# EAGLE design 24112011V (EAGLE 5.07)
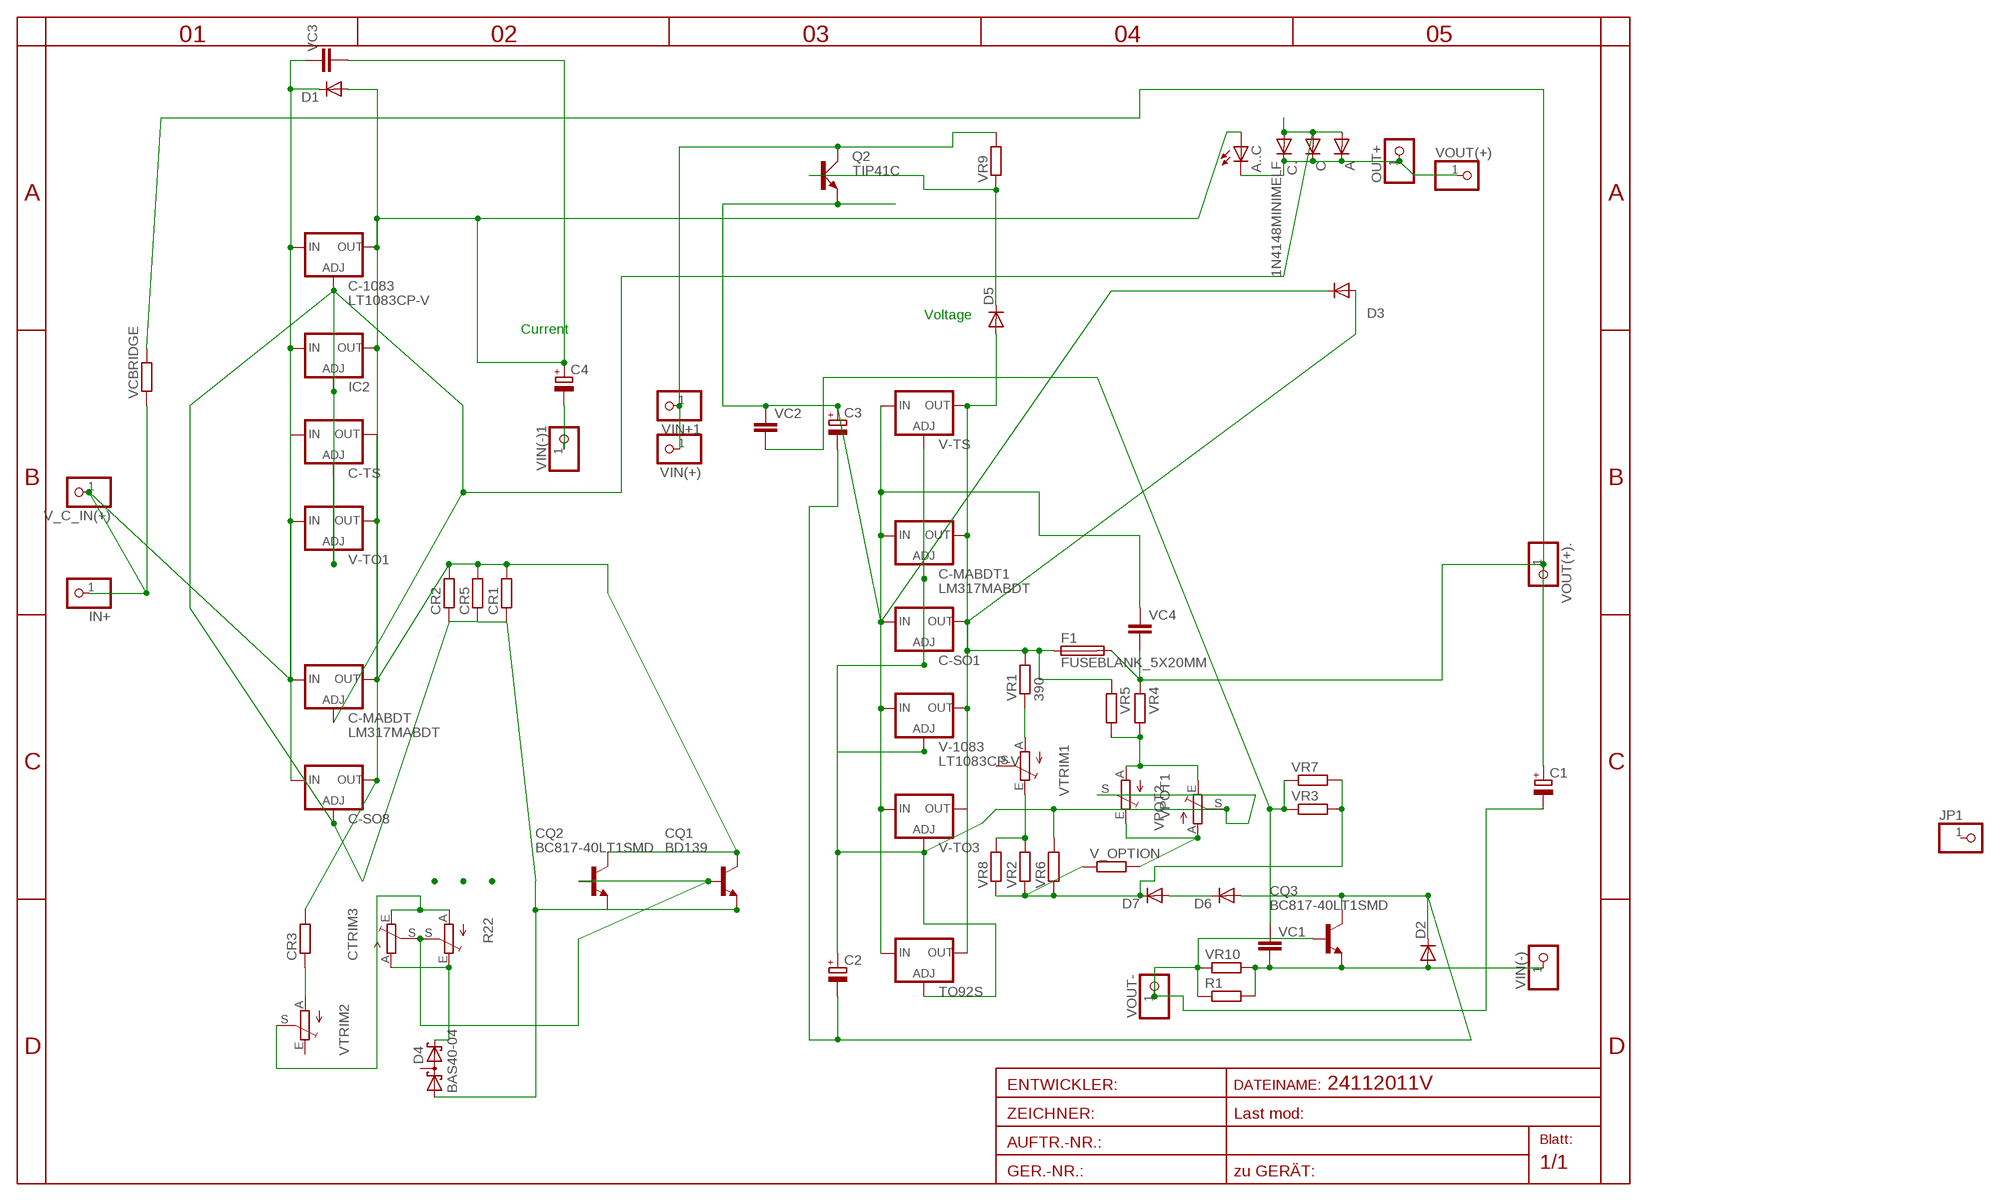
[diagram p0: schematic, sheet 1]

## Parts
A  DIODE-TO220V  [TO220ACS]
A..C  LED3MM  [LED3MM]
C  DIODE-SMB  [SMB]
C1  CPOL-EUE5-8.5  [E5-8,5]
C2  CPOL-EUE2.5-6  [E2,5-6]
C3  CPOL-EUE2.5-6  [E2,5-6]
C4  CPOL-EUE5-6  [E5-6]
C-1083  LT1083CP-V  [TO247S]
C-MABDT  LM317MABDT  [DPACK]
C-MABDT1  LM317MABDT  [DPACK]
C-SO1  LM317LM-OUTPIN7  [SO08]
C-SO8  LM317LM-OUTPIN7  [SO08]
C-TS  LM317TS  [317TS]
C.  1N4148MINIMELF  [MINIMELF]
CQ1  BD139  [TO126V]
CQ2  BC817-40LT1SMD  [SOT23-BEC]
CQ3  BC817-40LT1SMD  [SOT23-BEC]
CR1  R-EU_R5025  [R5025]
CR2  R-EU_R1206  [R1206]
CR3  R-EU_0204/5  [0204/5]
CR5  R-EU_R1210  [R1210]
CTRIM3  TRIM_EU-EVND_H  [EVND8AA]
D1  DIODE-MINIMELF  [MINIMELF]
D2  DIODE-MINIMELF  [MINIMELF]
D3  DIODE-MINIMELF  [MINIMELF]
D4  BAS40-04  [SOT23]
D5  DIODE-MINIMELF  [MINIMELF]
D6  DIODE-MINIMELF  [MINIMELF]
D7  DIODE-MINIMELF  [MINIMELF]
F1  FUSEBLANK_5X20MM  [FUSE_HOLDER_5X20MM]
IC2  LM317LZS  [TO92S]
IN+  PINHD-1X1  [1X01]
JP1  PINHD-1X10MM8  [1X01]
OUT+  PINHD-1X1  [1X01]
Q2  TIP41C  [TO220AV]
R1  R-EU_  [CERAM40]
R22  TRIM_EU-RAND160  [RANDL]
TO92S  LM317LZS  [TO92S]
V-1083  LT1083CP-V  [TO247S]
V-TO1  LM317-TO3  [TO3-K02]
V-TO3  LM317-TO3  [TO3-K02]
V-TS  LM317TS  [317TS]
V_C_IN(+)  PINHD-1X10MM8  [1X01]
V_OPTION  R-EU_0204/2V  [0204V]
VC1  C-EU050-025X075  [C050-025X075]
VC2  C-EU050-025X075  [C050-025X075]
VC3  C-EU050-025X075  [C050-025X075]
VC4  C-EUC1206  [C1206]
VCBRIDGE  R-EU_R0402  [R0402]
VIN(+)  PINHD-1X10MM8  [1X01]
VIN(-)  PINHD-1X1  [1X01]
VIN(-)1  PINHD-1X1  [1X01]
VIN+1  PINHD-1X1  [1X01]
VOUT(+)  PINHD-1X10MM8  [1X01]
VOUT(+).  PINHD-1X10MM8  [1X01]
VOUT-  PINHD-1X10MM8  [1X01]
VPOT1  TRIM_EU-RAND160  [RANDL]
VPOT2  TRIM_EU-S64W  [S64W]
VR1  390  R-EU_0207/15  [0207/15]
VR2  R-EU_0204/2V  [0204V]
VR3  R-EU_0204/5  [0204/5]
VR4  R-EU_R1206  [R1206]
VR5  R-EU_R1206  [R1206]
VR6  R-EU_R1206  [R1206]
VR7  R-EU_R1206  [R1206]
VR8  R-EU_R1206  [R1206]
VR9  R-EU_R1206  [R1206]
VR10  R-EU_0617/17  [0617/17]
VTRIM1  TRIM_EU-EVND_H  [EVND8AA]
VTRIM2  TRIM_EU-EVND_H  [EVND8AA]

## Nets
ADJ2: C2.+ C-MABDT1.1(ADJ) C-SO1.4(ADJ) TO92S.1(ADJ) V-1083.1(ADJ) V-TO3.2(ADJ) V-TS.1(ADJ) VPOT1.S VPOT2.S VR6.2
ADJUST: A.A C-1083.1(ADJ) C-MABDT.1(ADJ) C-SO8.4(ADJ) C-TS.1(ADJ) C..A C.A CQ1.3(E) CQ2.E CR1.1 CR2.1 CR5.1 D4.1(A1) IC2.1(ADJ) V-TO1.2(ADJ)
B1: CQ1.1(B) CQ2.B CTRIM3.S R22.S
IN+1: C3.+ C-MABDT1.3(IN) C-SO1.1(IN) D3.C Q2.E TO92S.3(IN) V-1083.3(IN) V-TO3.1(IN) V-TS.3(IN) VC2.1 VC4.1
IN-: CQ3.E D2.A R1.2 VC1.2 VIN(-).1 VR10.2
INPUT+: C-1083.3(IN) C-MABDT.3(IN) C-SO8.1(IN) C-TS.3(IN) D1.C IC2.3(IN) IN+.1 V-TO1.1(IN) V_C_IN(+).1 VC3.1 VCBRIDGE.1
MINUS: CTRIM3.A D4.2(C2) R22.E
N$1: V_OPTION.2 VPOT1.E VPOT2.A
N$2: VPOT1.A VPOT2.E VR4.2 VR5.2
N$3: VR2.2 VR8.2 VTRIM1.E
N$4: VR1.1 VTRIM1.A
N$5: CTRIM3.E R22.A VTRIM2.S
N$6: CR3.1 VTRIM2.A
N$7: VC1.1 VC2.2 VR3.1 VR7.1
N$8: Q2.C VIN(+).1 VIN+1.1 VR9.2
N$9: C4.- VIN(-)1.1
N$10: D5.C Q2.B VR9.1
N$11: C1.- CQ3.B R1.1 VOUT-.1 VR10.1
N$12: D7.C V_OPTION.1 VR2.1 VR3.2 VR6.1 VR7.2 VR8.1
N$13: D6.C D7.A
OUT1: A..C.A C4.+ C-1083.2(OUT) C-MABDT.4(OUT) C-SO8.7(OUT) C-TS.2(OUT) CQ1.2(C) CQ2.C CR1.2 CR2.2 CR3.2 CR5.2 D1.A IC2.2(OUT) V-TO1.3(OUT) VC3.2
OUT2: C-MABDT1.4(OUT) C-SO1.7(OUT) D3.A D5.A F1.1 TO92S.2(OUT) V-1083.2(OUT) V-TO3.3(OUT) V-TS.2(OUT) VR1.2 VR5.1
OUT+: A..C.K(C) A.C C..C C.C OUT+.1 VOUT(+).1
VIRT-: C2.- C3.- CQ3.C D2.C D6.A
VOUT+: C1.+ F1.2 VC4.2 VCBRIDGE.2 VOUT(+)..1 VR4.1
Unconnected: D4.3(C1A2) JP1.1 VTRIM1.S VTRIM2.E

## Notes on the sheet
- Voltage
- Current

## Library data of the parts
A C D1-D3 D5-D7 = diode:DIODE-: DIODE
A..C = led:LED: LED
C1-C4 = rcl:CPOL-EU: POLARIZED CAPACITOR, European symbol
C-1083 V-1083 = linear-technology-2:LT1083*: 7.5A Low Dropout Positive Adjustable Regulators
C-MABDT C-MABDT1 = v-reg:LM317?*: 500 mA Adjustable Output Positive Voltage Regulator Source: http://www.onsemi.co.jp .. LM317M-D.PDF
C-SO1 C-SO8 IC2 TO92S = v-reg-3:LM317L: Adjustable Voltage Regulator, 1.2V to 37V, 100mA
C-TS V-TS = v-reg:LM317TS: VOLTAGE REGULATOR
C. = diode-1:1N4148: DIODE
CQ1 = transistor-npn:BD139*: NPN Transistor
CQ2 CQ3 = transistor-npn:BC817*: NPN Transistor
CR1-CR3 CR5 V_OPTION VCBRIDGE VR1-VR10 = rcl-2:R-EU_: RESISTOR, European symbol
CTRIM3 R22 VPOT1 VPOT2 VTRIM1 VTRIM2 = pot:TRIM_EU-: POTENTIOMETER
D4 = diode:BAS40-04: Silicon Schottky Diodes General-purpose diode for high-speed switching
F1 = fuse:FUSE: Fuse
IN+ OUT+ VIN(-) VIN(-)1 VIN+1 = pinhead(2):PINHD-1X1: PIN HEADER
JP1 V_C_IN(+) VIN(+) VOUT(+) VOUT(+). VOUT- = pinhead:PINHD-1X1: PIN HEADER
Q2 = transistor-power:TIP41C: NPN TRANSISTOR
R1 = rcl:R-EU_: RESISTOR, European symbol
V-TO1 V-TO3 = v-reg:LM317-TO3: VOLTAGE REGULATOR
VC1-VC4 = rcl:C-EU: CAPACITOR, European symbol

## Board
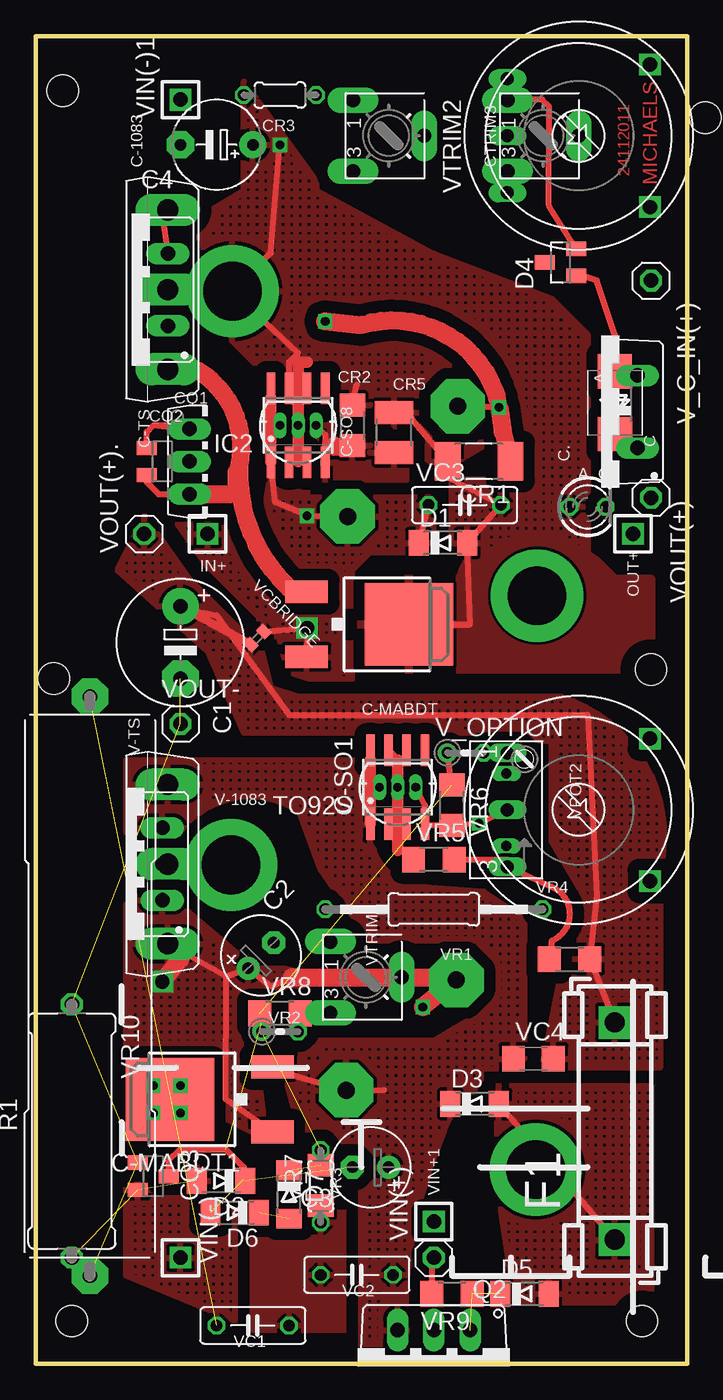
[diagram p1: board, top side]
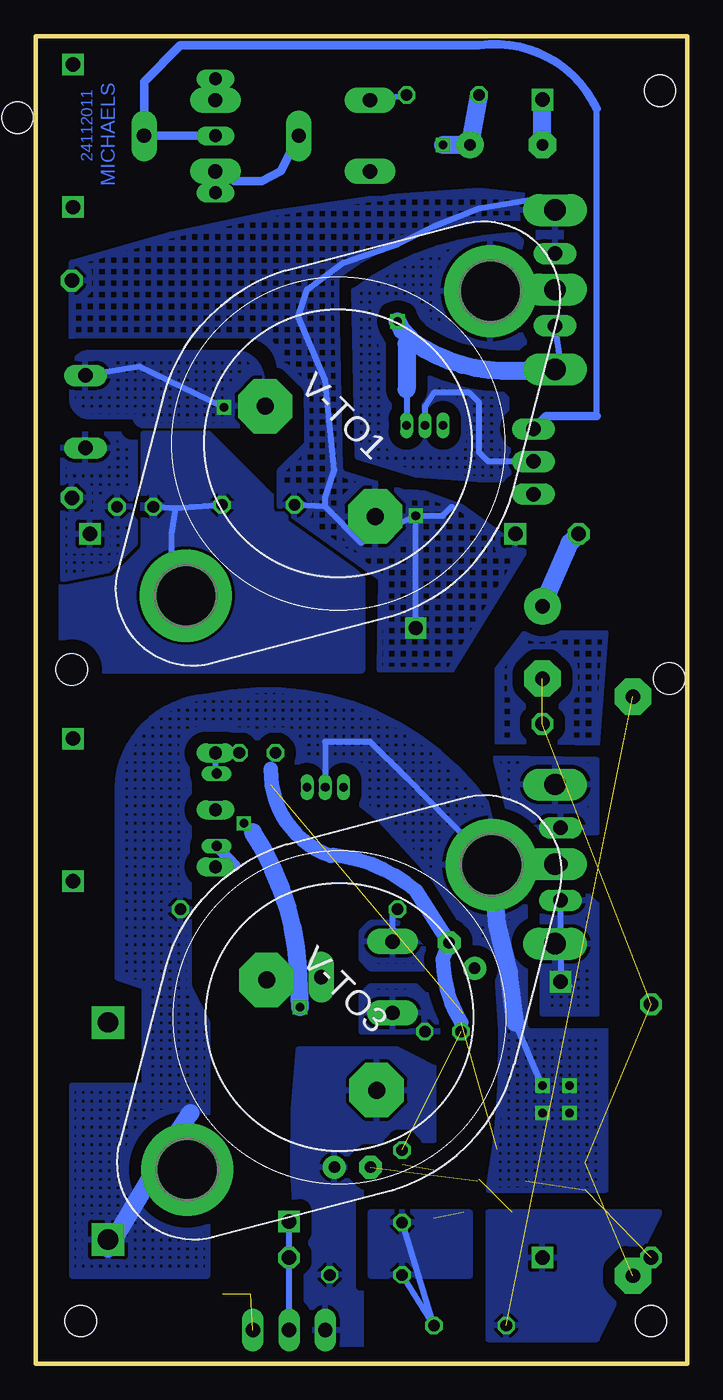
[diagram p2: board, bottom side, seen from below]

Size 45.72 x 93.18 mm. Coordinates in mm from the lower left corner, seen from the top.
Outline: 45.72,0 45.72,93.18 0,93.18 0,0 45.72,0
Copper layers (1*16): Top 0.035mm / dielectric 1.5mm / Bottom 0.035mm
Design rules "default *": minimum track width 10mil, minimum drill 24mil, track to track 8mil, track to pad 8mil, pad to pad 8mil, via to via 8mil, smd to smd 8mil, copper to edge 40mil, drill to drill 8mil, minimum pad ring 1mil, minimum via ring 8mil, stop-mask expansion 4mil, vias tented up to drill 0mil, thermal gap 10mil
Holes 2.2 mm at 46.99,87.46 1.27,48.09 43.18,48.73 1.91,89.37 42.55,3.01 2.54,3.01

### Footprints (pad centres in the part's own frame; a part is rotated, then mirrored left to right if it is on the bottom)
TO220ACS = drill 1.016 long: A 2.54,-2.54; C -2.54,-2.54
LED3MM = drill 0.813 octagon: A -1.27,0; K 1.27,0
SMB = smd 2.4 x 2.4: A 2.2,0; C -2.2,0
E5-8,5 = drill 1.016 pad 2.54 round: + -2.54,0 | drill 1.016 pad 2.54 octagon: - 2.54,0
E2,5-6 = drill 0.813 pad 1.6 round: + -1.27,0 | drill 0.813 pad 1.6 octagon: - 1.27,0
E5-6 = drill 0.813 pad 1.905 round: + -2.54,0 | drill 0.813 pad 1.905 octagon: - 2.54,0
TO247S = drill 1.499 long: 1 -5.588,-2.921; 2 0,-2.921; 3 5.588,-2.921
DPACK = smd 1.6 x 3: 1 -2.28,-4.8; 3 2.28,-4.8 | smd 5.8 x 6.2: 4 0,2.38
SO08 = smd 0.6 x 2.2: 1 -1.905,-2.6; 2 -0.635,-2.6; 3 0.635,-2.6; 4 1.905,-2.6; 5 1.905,2.6; 6 0.635,2.6; 7 -0.635,2.6; 8 -1.905,2.6
317TS = drill 1.016 long: 1 -2.54,-2.54; 2 0,-2.54; 3 2.54,-2.54
MINIMELF = smd 1.4 x 1.8: A 1.7,0; C -1.7,0
TO126V = drill 1.016 long: 1 -2.286,-1.27; 2 0,-1.27; 3 2.286,-1.27
SOT23-BEC = smd 1 x 1.4: B -0.95,-1.1; C 0,1.1; E 0.95,-1.1
R5025 = smd 1.8 x 2.7: 1 -2.2,0; 2 2.2,0
R1206 = smd 1.6 x 1.803: 1 -1.422,0; 2 1.422,0
0204/5 = drill 0.813 octagon: 1 -2.54,0; 2 2.54,0
R1210 = smd 1.6 x 2.7: 1 -1.4,0; 2 1.4,0
EVND8AA = drill 1 pad 1.778 long: A -2.5,-2.5; E 2.5,-2.5; S 0,2.5
SOT23 = smd 1 x 1.4: 1 -0.95,-1.1; 2 0.95,-1.1; 3 0,1.1
FUSE_HOLDER_5X20MM = drill 1.422 pad 2.286 square: 1 0,0; 2 15.24,0
TO92S = drill 0.6 pad 0.813 long: 1 -1.27,0; 2 0,0; 3 1.27,0
1X01 = drill 1.016 square: 1 0,0
1X01' = drill 1.016 octagon: 1 0,0
TO220AV = drill 1.016 long: B -2.54,-2.54; C 0,-2.54; E 2.54,-2.54
CERAM40 = drill 1 pad 2.54 octagon: 1 -20.32,0; 2 20.32,0
RANDL = drill 0.9 long: A -4,5; E 4,5; S 0,5 | drill 1 square: P$1 -5,-5; P$2 5,-5
TO3-K02 = drill 1.194 pad 3.81 octagon: 1 -1.778,-5.461; 2 -1.778,5.461 | drill 4.115 pad 6.477 round: 3 15.113,0; 3@ -15.113,0
0204V = drill 0.813 octagon: 1 -1.27,0; 2 1.27,0
C050-025X075 = drill 0.813 octagon: 1 -2.54,0; 2 2.54,0
C1206 = smd 1.6 x 1.8: 1 -1.4,0; 2 1.4,0
R0402 = smd 0.7 x 0.9: 1 -0.65,0; 2 0.65,0
S64W = drill 0.7 long: A 2.54,1.27; E -2.54,1.27; S 0,1.27
0207/15 = drill 0.813 octagon: 1 -7.62,0; 2 7.62,0
0617/17 = drill 1.016 octagon: 1 -8.89,0; 2 8.89,0

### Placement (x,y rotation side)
A  39.69,66.83 90 top
A..C  38.73,60.16 0 top
C  40.64,67.46 90 top
C1  10.16,50.63 270 top
C2  15.81,28.66 45 top
C3  23.5,13.81 180 top
C4  12.7,85.56 180 top
C-1083  6.35,75.4 90 top
C-MABDT  23.81,51.91 270 top
C-MABDT1  11.81,18.57 90 top
C-SO1  25.4,40.48 0 top
C-SO8  18.41,65.88 0 top
C-TS  6.73,75.4 90 top
C.  40.96,67.46 90 top
CQ1  12.06,63.34 270 top
CQ2  8.89,63.34 270 top
CQ3  8.26,13.17 270 top
CR1  31.11,63.34 180 top
CR2  22.23,65.88 90 top
CR3  17.14,89.05 180 top
CR5  25.15,65.37 90 top
CTRIM3  35.61,86.19 270 top
D1  28.57,57.62 0 top
D2  13.02,12.85 180 top
D3  30.8,18.25 0 top
D4  36.83,77.3 90 top
D5  34.29,4.92 0 top
D6  13.97,10.63 180 top
D7  17.78,11.9 270 top
F1  40.64,8.73 90 top
IC2  18.41,65.88 180 top
IN+  12.06,58.26 90 top
JP1  [1X01']  not placed on the board
OUT+  41.91,58.26 180 top
Q2  27.94,-0.17 180 top
R1  3.81,26.51 90 top
R22  38.1,86.19 90 top
TO92S  25.4,40.48 180 top
V-1083  6.35,35.08 90 top
V-TO1  24.5,64.6 45 bottom
V-TO3  24.4,24.33 45 bottom
V-TS  6.35,35.08 90 top
V_C_IN(+)  [1X01']  43.18,76.03 90 top
V_OPTION  30.16,42.89 0 top
VC1  15.24,2.69 180 top
VC2  22.54,6.25 180 top
VC3  30.1,60.29 0 top
VC4  34.92,21.43 0 top
VCBRIDGE  15.56,50.95 225 top
VIN(+)  [1X01']  27.94,7.46 90 top
VIN(-)  10.16,7.46 90 top
VIN(-)1  10.16,88.73 90 top
VIN+1  27.94,10 90 top
VOUT(+)  [1X01']  43.18,60.8 90 top
VOUT(+).  [1X01']  7.62,58.26 90 top
VOUT-  [1X01']  10.16,44.92 0 top
VPOT1  38.1,38.89 90 top
VPOT2  34.29,38.89 90 top
VR1  27.94,31.9 0 top
VR2  17.14,23.33 0 top
VR3  20,12.47 90 top
VR4  37.47,28.41 180 top
VR5  27.94,35.4 0 top
VR6  29.21,39.2 270 top
VR7  20,12.54 90 top
VR8  17.14,24.6 0 top
VR9  29.21,4.92 180 top
VR10  2.54,16.35 270 top
VTRIM1  23.18,27.14 270 top
VTRIM2  24.77,86.19 270 top

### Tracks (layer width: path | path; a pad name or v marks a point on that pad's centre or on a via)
ADJ2  (via drill 0.6, 1)
  Top 0.406: TO92S.1 27.3,39.2 C-SO1.4 27.3,37.78 VR6.2 v31.11,37.94 VPOT2.S VPOT1.S | 17.98,27.14 16.51,26.51 C2.+ 13.36,27.2 | 13.36,27.2 V-1083.1 | C-MABDT1.1 13.34,18.57 13.36,27.2 | 29.84,27.14 V-TO3.2
  Top 1.27: v8.89,26.82 10.16,28.41 | 17.98,27.14 29.84,27.14 | V-TO3.2 v27.16,25.04
  Bottom 0.406: 9.62,29.14 V-1083.1 8.89,29.87 V-TS.1 | 9.62,29.14 10.16,28.6 | 9.62,29.14 8.89,28.41 v8.89,26.82 8.26,26.51 | 30.48,37.3 v31.11,37.94
  Bottom 1.27: 30.48,37.3 arc30 27.3,27.78 v27.16,25.04
  pour Bottom (isolate 0.813, hatched): 10.16,24.6 6.35,24.6 6.35,32.22 7.62,33.49 10.16,33.49
  pour Top (isolate 0.813, hatched): 6.35,20.79 6.35,32.22 7.62,33.49 8.89,33.49 10.16,32.22 14.61,28.41 20.32,27.14 15.24,25.23 15.24,23.33 16.19,15.71
ADJUST  (via drill 0.6)
  Top 0.406: CQ2.E 7.79,61.9 8.64,61.05 CQ1.3 | 22,64.23 CR2.1 | V-TO1.2 30.31,67.14 v32.51,67.14 32.38,67.78 | 20.32,64.6 C-SO8.4 | 20.32,64.6 20.32,65.24 IC2.1 | 39.91,69.75 40.55,69.75 C.A | D4.1 38.41,76.35 39.37,76.03 40.64,72.22 C.A | A.A C..A C.A | 20.32,64.6 20.95,64.6
  Top 1.016: 13.59,61.05 13.97,61.43 13.97,62.64 14.29,62.95 | 22,64.23 20.95,64.23 20.95,64.6
  Top 1.27: v20.32,73.18 22.86,72.92 arc-90 32.38,67.78 | CR1.1 32.77,65.43 v32.51,67.14 | C-MABDT.1 18.68,54.19 17.78,54.45 arc-49 14.29,62.95 arc71 11.43,69.68 10.03,69.68 C-1083.1 | CQ1.3 13.59,61.05
  Bottom 0.406: C-TS.1 8.89,70.19 C-1083.1 10.03,69.05 | A.A 38.42,70 v32.51,67.14 | 19.68,68.41 IC2.1
  Bottom 1.27: 19.68,68.41 19.68,71.59 19.24,71.72 | v20.32,73.18 20,72.54 19.24,71.72 | 19.24,71.72 arc-37 12.06,69.68 10.16,69.68 C-1083.1
  pour Bottom (isolate 0.813, hatched): 29.84,69.05 arc-90 31.75,70.95 41.91,70.95 arc-90 43.18,69.68 43.18,67.78 arc-90 41.91,66.51 38.73,66.51 arc-90 38.1,65.88 29.84,65.88
  pour Top (isolate 0.61): 19.68,62.06 26.04,62.06 26.04,63.97 20.95,65.24 20.95,65.88 19.68,65.88
B1
  Top 0.406: CQ2.B 7.79,65.41 8.26,65.88 | 8.26,65.88 10.54,65.88 CQ1.1 8.26,65.88
  Bottom 0.406: 6.35,66.51 6.35,88.1
  Bottom 0.61: 6.35,88.1 arc-73 14.61,92.54 35.56,92.54 38.1,90 CTRIM3.S R22.S | 6.35,66.51 9.91,66.51 CQ1.1
IN+1
  Top 0.406: 24.43,19.22 V-TO3.1 18.41,20.16 C-MABDT1.3 | TO92S.3 23.5,39.2 23.5,37.94 C-SO1.1
  Top 0.813: 23.5,37.94 23.5,42.38
  pour Bottom (isolate 0.813, hatched): 6.35,37.3 6.35,42.38 13.46,42.51 12.19,37.43
  pour Top (isolate 0.813, rank 3, hatched): 22.86,1.1 22.86,13.17 18.73,15.71 16.83,22.7 27.94,22.7 31.11,24.6 31.11,29.68 23.5,29.68 20,34.7 18.54,38.7 arc90 10.16,37.3 6.35,37.3 6.35,42.38 22.23,42.38 23.5,43.02 23.5,37.3 arc90 27.3,33.49 31.43,33.17 34.29,31.27 34.29,21.43 32.38,19.52 29.84,18.89 arc32 26.04,1.1
  pour Bottom (isolate 0.813, rank 4): 20.32,22.06 27.3,22.06 arc-20 26.04,1.1 22.86,1.1 22.86,14.44 21.59,15.71 17.78,15.71 17.78,20.79
IN-  (3 unrouted)
  pour Bottom (isolate 0.813, rank 2): 6.35,1.74 1.91,10.63 13.97,10.63 13.97,1.74
  pour Top (isolate 0.813, hatched): 6.35,6.18 6.35,13.81 12.06,13.81 12.06,12.54 13.97,10.63 13.97,3.01
  pour Bottom (isolate 0.813, rank 3, hatched): 5.71,51.27 11.43,51.27 13.34,48.73 13.34,43.02 6.35,43.02
  pour Top (isolate 0.813, rank 4, hatched): 5.71,51.27 11.43,51.27 13.34,48.73 13.34,43.02 6.35,43.02
INPUT+  (via drill 0.6, 1)
  Top 0.406: C-SO8.1 16.83,60.48 v19.05,59.52 V-TO1.1 | C-TS.3 8.89,80.61 C-1083.3 | VC3.1 D1.C | 16.51,65.88 IC2.3 | C-SO8.1 16.51,62.7 | C-SO8.1 16.51,63.34 | C-MABDT.3 v19.05,51.65 VCBRIDGE.1
  Top 0.813: 16.51,63.34 16.51,65.88 16.51,67.78
  Bottom 0.406: 12.06,57.62 IN+.1 | C-1083.3 10.03,81.75 10.79,81.75 14.61,81.11 17.78,79.84 20.32,78.57 24.13,77.3 26.67,75.4 27.3,73.49 25.4,69.05 24.77,62.7 25.4,60.8 25.4,60.16 | v19.05,59.52 22.86,57.62 25.4,60.16 | 16.51,60.16 17.14,59.52 v19.05,59.52 | 25.4,60.16 VC3.1 | v19.05,51.65 v19.05,59.52
  pour Top (isolate 0.813, rank 2, hatched): 22.23,48.09 22.23,55.72 23.5,56.98 27.94,56.98 27.94,60.8 26.67,60.8 26.04,61.43 17.78,61.43 17.78,62.06 17.14,62.7 16.51,62.7 15.88,58.89 9.53,58.89 17.78,48.09
  pour Bottom (isolate 0.813, rank 2, hatched): 11.43,56.98 16.51,48.73 21.59,48.73 21.46,55.08 28.57,60.16 28.57,62.7 26.67,64.6 26.67,67.14 29.84,71.59 43.18,71.59 43.18,77.3 arc16 14.61,82.38 8.89,81.75 8.89,77.94 18.41,77.94 24.13,74.13 23.5,63.97 22.86,62.7 15.88,60.16
MINUS
  Top 0.406: D4.2 36.01,81.31 36.02,88.27 35.56,88.73 33.15,88.73 CTRIM3.A
  Bottom 0.406: R22.E CTRIM3.A
N$1
  Bottom 0.406: VPOT2.A 33.1,41.43 VPOT1.E 32.26,42.89 V_OPTION.2
N$2
  Top 0.406: VR5.2 33.1,35.4 VPOT1.A 36.2,33.49 arc-135 36.2,29.68 VR4.2
  Bottom 0.813: VPOT2.E 31.75,34.97 VPOT1.A
N$3
  Top 0.406: VR8.2 VTRIM1.E
  Bottom 0.813: VTRIM1.E 20.64,24.6
  pour Bottom (isolate 0.813, rank 2, hatched): 17.14,23.33 17.14,25.23 17.46,25.87 18.41,25.87 19.05,26.51 22.23,26.51 22.86,25.87 22.86,23.33
N$4
  Bottom 0.406: VR1.1 20.68,31.9 20.68,30.28
  Bottom 0.813: VTRIM1.A 20.68,30.28
  pour Bottom (isolate 0.813, rank 3, hatched): 17.78,27.78 17.78,28.41 20.32,30.95 22.23,30.95 22.86,30.32 22.86,28.41 22.23,27.78
N$5
  Bottom 0.406: 31.8,83.02 CTRIM3.E R22.A
  Bottom 0.61: VTRIM2.S 28.54,83.69 29.84,83.02 31.8,83.02
N$6
  Bottom 0.406: VTRIM2.A CR3.1
N$7
  Top 0.406: VR3.1 VR7.1
  Bottom 0.406: VR3.1 VC1.1 VC2.2
  pour Bottom (isolate 0.813, rank 3): 15.24,10.63 22.23,10.63 22.23,6.18 15.24,6.18
  pour Top (isolate 0.813, rank 4): 15.24,10.63 22.23,10.63 22.23,2.38 15.24,2.38
N$8
  Top 0.406: VR9.2 27.79,7.3 VIN(+).1
  Bottom 0.406: VIN+1.1 VIN(+).1 Q2.C
N$9
  Bottom 1.27: C4.- VIN(-)1.1
N$10  (2 unrouted)
N$11  (4 unrouted)
N$12  (3 unrouted)
  Top 0.406: VR7.2 VR3.2 | VR6.1 V_OPTION.1 | VR8.1 VR2.1
N$13  (1 unrouted)
OUT1  (via drill 0.6)
  Top 0.406: CQ2.C CQ1.2 | v17.14,85.56 16.51,77.99 V-TO1.3 | C-1083.2 13.7,75.4 V-TO1.3 | IC2.2 18.41,67.14 17.78,67.78 C-SO8.7 17.78,70.32 18.1,70.64 | CR2.2 22.54,68.73 | 18.1,70.64 18.41,70.95 V-TO1.3 | C-MABDT.4 30.48,51.91 D1.A VC3.2 29.21,62.06 CR1.2 26.61,66.07 25.92,66.96 CR5.2 | 18.41,70.32 18.1,70.32 18.1,70.64
  Top 0.813: 19.05,70.32 18.41,70.32 18.41,63.34
  Bottom 0.406: 35.94,60.03 36.2,58.26 36.2,56.35 | 35.94,60.03 A..C.A | CQ2.C CQ1.2 13.97,63.34 14.61,63.97 14.61,67.46 15.3,68.16 17.78,68.16 18.41,67.2 IC2.2 | VC3.2 35.94,60.03
  Bottom 1.27: v17.14,85.56 C4.+ CR3.2
  pour Top: 22.86,55.08 29.84,55.08 arc-90 31.75,56.98 arc-64 39.37,56.35 40.64,55.08 43.18,55.08 43.18,48.73 22.86,48.73
  pour Bottom (isolate 0.813, hatched): 7.62,74.77 8.89,74.77 11.43,72.22 11.43,71.59 12.06,70.95 16.51,70.95 13.34,68.41 12.7,67.78 12.7,65.24 10.79,63.34 9.53,63.34 10.16,62.7 12.7,62.06 14.61,62.06 18.99,62.38 23.11,63.65 23.37,75.34 arc33 12.7,79.21 12.06,79.21
  pour Top (isolate 0.813, rank 3, hatched): 38.73,56.35 30.48,56.35 29.21,57.62 29.21,62.06 31.75,62.06 31.75,64.6 28.57,62.7 26.67,63.97 24.13,67.14 18.41,67.14 11.43,74.13 11.43,80.48 14.61,82.38 14.61,90 19.68,83.02 19.68,82.38 27.94,77.94 36.2,74.77 38.73,72.22
  pour Bottom (rank 3): 22.86,55.08 29.84,61.43 33.66,65.24 38.1,65.24 38.1,59.52 40.01,55.72 43.81,55.72 43.81,48.73 22.86,48.73
OUT2  (via drill 0.6)
  Top 0.406: 25.4,42.38 25.46,42.38 C-SO1.7 | 25.4,36.03 26.52,36.03 VR5.1 | C-MABDT1.4 v10.16,19.52 | F1.1 D3.A
  Top 0.813: 25.4,42.38 TO92S.2 25.4,36.03
  Bottom 0.406: 9.32,35.02 V-1083.2 V-TS.2 | v10.16,19.52 12.06,23.96 | V-TO3.3 19.68,41.11 22.23,43.65 25.4,43.65 TO92S.2 | F1.1 40.64,8.09
  Bottom 1.27: 34.86,17.62 36.07,15.77 40.64,8.09 | V-1083.2 V-TO3.3 13.34,30.89 12.51,27.52 12.06,23.96
  other vias: 8.26,19.52 8.26,17.62 10.16,17.62
  pour Bottom (isolate 0.813, rank 6, hatched): 10.79,37.3 12.7,38.57 13.97,38.57 13.97,39.2 arc-68 33.66,46.83 arc-90 40.01,39.84 40.01,27.14 38.1,26.51 38.1,19.52 43.18,19.52 43.18,6.18 33.66,6.18 33.66,23.96 34.92,26.51 34.92,44.29 24.45,40.48 21.59,38.25 18.41,34.76 16.51,31.59 13.34,27.14 arc16 13.97,12.22 5.71,12.22 5.71,23.52 10.79,23.65
  pour Top (isolate 0.254, rank 2, hatched): 32.38,19.52 43.18,19.52 43.18,4.28 33.66,4.28 32.38,12.54
OUT+
  Top 0.406: A.C C..C C.C
  pour Bottom (isolate 0.813, rank 2, hatched): 38.73,65.24 43.81,65.24 43.81,55.08 40.64,55.72 38.73,57.62
VIRT-  (3 unrouted)
  Top 0.406: CQ3.C 9.36,14.27 10.16,15.08 13.34,15.08 14.61,13.81 14.61,12.97 D2.C
  Bottom 0.813: 24.83,35.71 25.02,35.65
  Bottom 1.016: 25.02,35.65 arc72 29.21,41.74 | 24.83,35.71 arc34 19.05,33.24 C2.- 17.14,28.41 arc-29 15.88,23.96
VOUT+
  Top 0.406: F1.2 VR4.1 39.37,32.86 38.73,45.55 17.78,45.55 12.7,52.54 9.53,53.18 C1.+
  Top 0.61: VCBRIDGE.2 C1.+
  Bottom 1.27: C1.+ 8.26,57.62 VOUT(+)..1
  pour Top (isolate 0.813, hatched): 5.71,55.72 7.62,59.52 10.79,55.08 15.88,50 16.51,47.46 18.41,46.83 36.83,46.83 arc-86 43.81,34.76 43.81,20.79 35.56,20.79 38.1,33.49 36.2,36.66 36.2,43.65 30.48,44.29 14.61,44.29 12.06,50

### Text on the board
Top: 24112011 | MICHAELS
Bottom: MICHAELS | 24112011
tNames: V_in(+) | V_out(+)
